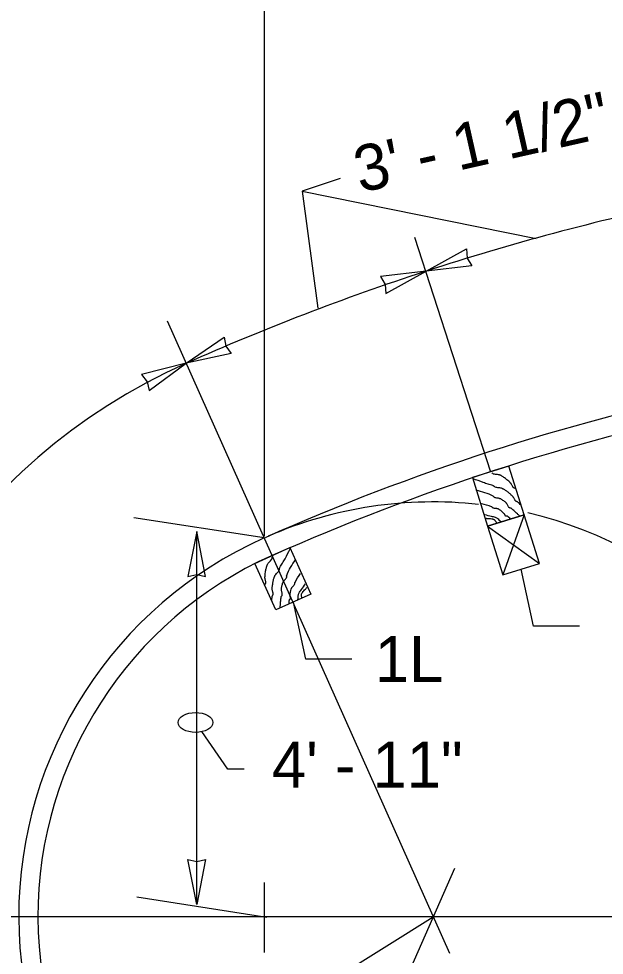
# Model space of a CAD drawing. Extents: x 1312564.2 to 1312581.5, y 1207298.4 to 1207352.6.
# Drawn here: x 1312566.218 to 1312567.233, y 1207306.924 to 1207308.547 of the extents above; entities that cross this region are included whole.
import ezdxf

# ---------------------------------------------------------------- set-up
doc = ezdxf.new("R2010")
doc.units = 0
for name, color, linetype in [('Level 13', 7, 'Continuous'), ('Level 14', 7, 'Continuous'), ('Level 15', 7, 'Continuous'), ('Level 20', 7, 'Continuous')]:
    doc.layers.add(name, color=color, linetype=linetype)

msp = doc.modelspace()

# ---------------------------------------------------------------- linework, layer by layer
at = {"layer": 'Level 13'}
for points in [[(1312567.0801831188, 1207307.7314976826), (1312567.0792387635, 1207307.732349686), (1312567.0788612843, 1207307.7326280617), (1312567.0784413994, 1207307.7328425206), (1312567.0775294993, 1207307.7331625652), (1312567.0766132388, 1207307.7334755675), (1312567.0761879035, 1207307.7336812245), (1312567.0758027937, 1207307.7339472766), (1312567.0750363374, 1207307.7347329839), (1312567.074407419, 1207307.7356371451), (1312567.0733904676, 1207307.7376581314), (1312567.0724084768, 1207307.7397248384), (1312567.07182326, 1207307.7406861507), (1312567.0711179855, 1207307.7415518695), (1312567.0701074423, 1207307.7425827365), (1312567.069083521, 1207307.74359835), (1312567.0626155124, 1207307.7493116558), (1312567.0579374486, 1207307.7526796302), (1312567.0554699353, 1207307.7542056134), (1312567.0542013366, 1207307.7549253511), (1312567.0529084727, 1207307.7556148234), (1312567.051294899, 1207307.7562446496), (1312567.0495871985, 1207307.7565974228), (1312567.0460449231, 1207307.7568778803), (1312567.042592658, 1207307.7572683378), (1312567.0409974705, 1207307.7577586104), (1312567.0395414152, 1207307.7585809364), (1312567.0380289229, 1207307.7597637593)], [(1312567.0888352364, 1207307.70378218), (1312567.083032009, 1207307.7090447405), (1312567.0822345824, 1207307.7095371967), (1312567.0813223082, 1207307.7098569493), (1312567.0804058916, 1207307.7101699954), (1312567.0795960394, 1207307.710642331), (1312567.078830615, 1207307.7114289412), (1312567.0782021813, 1207307.7123335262), (1312567.077185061, 1207307.7143543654), (1312567.0762022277, 1207307.716420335), (1312567.0752815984, 1207307.717828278), (1312567.0749112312, 1207307.7182469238), (1312567.0707931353, 1207307.7222832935), (1312567.0664286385, 1207307.726029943), (1312567.0617530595, 1207307.7294008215), (1312567.0592784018, 1207307.7309184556), (1312567.0580033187, 1207307.7316306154), (1312567.0567017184, 1207307.7323098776), (1312567.0550943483, 1207307.7329606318), (1312567.0534194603, 1207307.73338497), (1312567.0499658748, 1207307.7338472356), (1312567.0465384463, 1207307.7342823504), (1312567.0441038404, 1207307.7349431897), (1312567.0433346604, 1207307.7352759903), (1312567.0424580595, 1207307.7358484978), (1312567.0416447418, 1207307.7365543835), (1312567.040816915, 1207307.737235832), (1312567.0398967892, 1207307.7377350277), (1312567.0357424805, 1207307.7390843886), (1312567.031534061, 1207307.740295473), (1312567.0273303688, 1207307.7415275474), (1312567.0231902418, 1207307.7429398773), (1312567.0054866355, 1207307.7496751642)], [(1312567.0864377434, 1207307.684698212), (1312567.0822789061, 1207307.6887763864), (1312567.0797859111, 1207307.691163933), (1312567.077244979, 1207307.693502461), (1312567.0746719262, 1207307.6958037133), (1312567.072082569, 1207307.6980794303), (1312567.0717098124, 1207307.6983240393), (1312567.0712864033, 1207307.6984792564), (1312567.0703536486, 1207307.6986379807), (1312567.069416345, 1207307.6987885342), (1312567.068606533, 1207307.6991638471), (1312567.0681587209, 1207307.6995654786), (1312567.067754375, 1207307.700007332), (1312567.0670521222, 1207307.700990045), (1312567.0659056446, 1207307.7031998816), (1312567.0647837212, 1207307.7054468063), (1312567.0637277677, 1207307.7069478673), (1312567.0633029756, 1207307.7073842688), (1312567.0610276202, 1207307.7093902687), (1312567.0586327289, 1207307.711257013), (1312567.0561122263, 1207307.7129612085), (1312567.053460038, 1207307.7144795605), (1312567.0521457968, 1207307.7150303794), (1312567.05076426, 1207307.7153972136), (1312567.0478969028, 1207307.7158235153), (1312567.0450531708, 1207307.7162476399), (1312567.0437011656, 1207307.7166117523), (1312567.042428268, 1207307.7171587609), (1312567.041880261, 1207307.7176321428), (1312567.0414293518, 1207307.7182549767), (1312567.0409638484, 1207307.7188537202), (1312567.0403720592, 1207307.7192548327), (1312567.0111425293, 1207307.729577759)], [(1312567.070334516, 1207307.6796711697), (1312567.0646377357, 1207307.6847546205), (1312567.0643591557, 1207307.6849131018), (1312567.0640345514, 1207307.6849647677), (1312567.0633073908, 1207307.6848879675), (1312567.0625765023, 1207307.684804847), (1312567.0619621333, 1207307.6849960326), (1312567.061754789, 1207307.6851866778), (1312567.0615703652, 1207307.6853973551), (1312567.0612578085, 1207307.685868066), (1312567.0607705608, 1207307.6869317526), (1312567.0603008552, 1207307.6880152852), (1312567.0600102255, 1207307.6885108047), (1312567.0596491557, 1207307.6889468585), (1312567.058449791, 1207307.6901151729), (1312567.0572263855, 1207307.6912654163), (1312567.05467958, 1207307.6934675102), (1312567.050504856, 1207307.6963589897), (1312567.04975653, 1207307.696775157), (1312567.04899087, 1207307.6971688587), (1312567.0479593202, 1207307.6975677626), (1312567.0468838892, 1207307.6978082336), (1312567.044666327, 1207307.6980191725), (1312567.0424680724, 1207307.6982122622), (1312567.0409101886, 1207307.6985923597), (1312567.040662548, 1207307.6986893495), (1312567.0404190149, 1207307.6987980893), (1312567.0397158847, 1207307.6992674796), (1312567.039069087, 1207307.699857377), (1312567.0384068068, 1207307.7004186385), (1312567.0376572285, 1207307.700802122), (1312567.020162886, 1207307.7060446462)], [(1312567.054269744, 1207307.674656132), (1312567.0522416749, 1207307.6764684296), (1312567.0517878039, 1207307.6768861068), (1312567.051338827, 1207307.677319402), (1312567.048639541, 1207307.67999126), (1312567.0466931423, 1207307.681506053), (1312567.04448496, 1207307.682466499), (1312567.037516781, 1207307.6841813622), (1312567.0259177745, 1207307.6870358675)], [(1312567.046658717, 1207307.6722801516), (1312567.045875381, 1207307.673895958), (1312567.045060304, 1207307.675464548), (1312567.044122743, 1207307.6768509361), (1312567.0435796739, 1207307.6774336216), (1312567.0432846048, 1207307.6776899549), (1312567.0431305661, 1207307.6778084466), (1312567.0430518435, 1207307.6778651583), (1312567.0430120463, 1207307.6778928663), (1312567.0429920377, 1207307.6779065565), (1312567.0429719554, 1207307.6779201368), (1312567.0426034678, 1207307.6781535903), (1312567.0422221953, 1207307.6783680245), (1312567.0414238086, 1207307.6787435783), (1312567.0397012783, 1207307.6793076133), (1312567.0358940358, 1207307.679896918), (1312567.0318721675, 1207307.6801669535), (1312567.0298813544, 1207307.6803319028), (1312567.027957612, 1207307.6805966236)], [(1312566.6566299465, 1207307.5381493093), (1312566.657468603, 1207307.5459383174), (1312566.6577371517, 1207307.5468362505), (1312566.6582062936, 1207307.547681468), (1312566.6586829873, 1207307.5485244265), (1312566.6589741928, 1207307.5494155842), (1312566.6590233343, 1207307.5505120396), (1312566.6588917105, 1207307.551605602), (1312566.6583086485, 1207307.5537915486), (1312566.6576699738, 1207307.5559884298), (1312566.6574221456, 1207307.5576522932), (1312566.657420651, 1207307.5582112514), (1312566.6578151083, 1207307.5639641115), (1312566.6585862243, 1207307.5696642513), (1312566.6598395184, 1207307.5752903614), (1312566.6606799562, 1207307.5780689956), (1312566.661159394, 1207307.5794485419), (1312566.6616805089, 1207307.5808211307), (1312566.662449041, 1207307.5823756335), (1312566.6634184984, 1207307.5838058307), (1312566.6656917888, 1207307.586446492), (1312566.6679635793, 1207307.589049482), (1312566.669343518, 1207307.5911613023), (1312566.6696970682, 1207307.5919211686), (1312566.6699715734, 1207307.592931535), (1312566.6701101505, 1207307.5939995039), (1312566.6702758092, 1207307.5950588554), (1312566.67063156, 1207307.59604337), (1312566.6728388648, 1207307.5998125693), (1312566.6751785, 1207307.6035144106), (1312566.6775006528, 1207307.6072287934), (1312566.679655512, 1207307.6110356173), (1312566.6884073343, 1207307.627834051)], [(1312566.6446750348, 1207307.5646084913), (1312566.6448144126, 1207307.5658727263), (1312566.6449114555, 1207307.566331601), (1312566.6450826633, 1207307.5667709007), (1312566.6455513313, 1207307.5676160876), (1312566.6460279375, 1207307.5684589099), (1312566.6462090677, 1207307.568895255), (1312566.6463200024, 1207307.5693499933), (1312566.6463705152, 1207307.57044646), (1312566.646239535, 1207307.5715400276), (1312566.6456562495, 1207307.573725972), (1312566.645016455, 1207307.5759228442), (1312566.644814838, 1207307.5770300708), (1312566.6447664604, 1207307.5781456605), (1312566.6448364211, 1207307.579587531), (1312566.6449265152, 1207307.5810268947), (1312566.6459623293, 1207307.5895945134), (1312566.6472194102, 1207307.5952201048), (1312566.648048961, 1207307.5980002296), (1312566.648518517, 1207307.5993811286), (1312566.6490263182, 1207307.6007555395), (1312566.6498133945, 1207307.6022985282), (1312566.6508549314, 1207307.6036970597), (1312566.653315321, 1207307.6062608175), (1312566.6556353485, 1207307.6088469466), (1312566.6565014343, 1207307.6102734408), (1312566.6570428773, 1207307.611855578), (1312566.6573869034, 1207307.6137445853)], [(1312566.6711045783, 1207307.52548318), (1312566.6715016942, 1207307.5312943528), (1312566.6717776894, 1207307.5347351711), (1312566.67212208, 1207307.5381712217), (1312566.6725152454, 1207307.5416007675), (1312566.6729375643, 1207307.5450220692), (1312566.6730535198, 1207307.5454525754), (1312566.6732667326, 1207307.545849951), (1312566.6738581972, 1207307.5465884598), (1312566.6744584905, 1207307.5473238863), (1312566.6748141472, 1207307.5481425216), (1312566.6748818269, 1207307.5487402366), (1312566.6748902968, 1207307.549339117), (1312566.6747619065, 1207307.5505401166), (1312566.6741498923, 1207307.552953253), (1312566.6734948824, 1207307.5553777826), (1312566.673286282, 1207307.5572011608), (1312566.6733136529, 1207307.5578095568), (1312566.673680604, 1207307.56082064), (1312566.674229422, 1207307.5638071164), (1312566.6749801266, 1207307.5667556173), (1312566.6759527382, 1207307.5696527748), (1312566.6765686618, 1207307.570937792), (1312566.6773571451, 1207307.572130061), (1312566.6792163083, 1207307.574354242), (1312566.6810592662, 1207307.5765610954), (1312566.6818274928, 1207307.5777317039), (1312566.6824150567, 1207307.5789863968), (1312566.6825099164, 1207307.5797043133), (1312566.6824328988, 1207307.5804693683), (1312566.682382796, 1207307.5812261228), (1312566.6825584, 1207307.5819191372), (1312566.697538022, 1207307.6090583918)], [(1312566.6864778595, 1207307.5324292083), (1312566.6873560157, 1207307.5400136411), (1312566.6874588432, 1207307.5403172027), (1312566.6876670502, 1207307.5405715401), (1312566.688261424, 1207307.5409974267), (1312566.6888627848, 1207307.5414210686), (1312566.689194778, 1207307.5419722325), (1312566.6892230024, 1207307.5422524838), (1312566.689220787, 1207307.5425324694), (1312566.6891414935, 1207307.5430919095), (1312566.6887986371, 1207307.5442105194), (1312566.6884294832, 1207307.5453323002), (1312566.688317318, 1207307.545895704), (1312566.688297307, 1207307.5464614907), (1312566.6884170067, 1207307.5481315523), (1312566.6885666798, 1207307.5498040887), (1312566.6890061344, 1207307.5531420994), (1312566.6902037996, 1207307.5580771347), (1312566.6904863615, 1207307.5588854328), (1312566.6907968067, 1207307.5596884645), (1312566.6913024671, 1207307.5606720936), (1312566.6919462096, 1207307.5615665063), (1312566.6934629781, 1207307.5631979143), (1312566.694977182, 1207307.5648031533), (1312566.695888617, 1207307.5661225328), (1312566.6960091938, 1207307.5663595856), (1312566.696118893, 1207307.5666026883), (1312566.6963323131, 1207307.567420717), (1312566.6964235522, 1207307.5682913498), (1312566.6965453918, 1207307.569150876), (1312566.696850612, 1207307.5699355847), (1312566.7064381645, 1207307.585479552)], [(1312566.7018144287, 1207307.5393586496), (1312566.7021253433, 1207307.542060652), (1312566.702186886, 1207307.5426743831), (1312566.7022343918, 1207307.543296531), (1312566.7024755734, 1207307.5470868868), (1312566.7029231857, 1207307.5495123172), (1312566.7039348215, 1207307.5516975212), (1312566.7080017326, 1207307.5576099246), (1312566.714771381, 1207307.5674515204)], [(1312566.7090804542, 1207307.5426416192), (1312566.708591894, 1207307.544369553), (1312566.7081584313, 1207307.5460833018), (1312566.70793758, 1207307.5477423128), (1312566.7079561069, 1207307.5485386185), (1312566.7080062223, 1207307.5489262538), (1312566.7080425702, 1207307.549117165), (1312566.7080637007, 1207307.549211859), (1312566.708075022, 1207307.5492590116), (1312566.708080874, 1207307.5492825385), (1312566.7080868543, 1207307.5493060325), (1312566.708207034, 1207307.5497253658), (1312566.7083494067, 1207307.550138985), (1312566.7086963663, 1207307.5509502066), (1312566.7096085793, 1207307.5525164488), (1312566.7120616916, 1207307.5554870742), (1312566.7148873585, 1207307.5583617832), (1312566.716265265, 1207307.5598081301), (1312566.7175267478, 1207307.5612844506)]]:
    msp.add_spline(points, degree=3, dxfattribs=at)
at = {"layer": 'Level 14'}
for p, q in [((1312567.0940508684, 1207307.6870748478), (1312567.0571052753, 1207307.5828537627)), ((1312567.0307398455, 1207307.6673106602), (1312567.120416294, 1207307.6026179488))]:
    msp.add_line(p, q, dxfattribs=at)
at = {"layer": 'Level 15'}
for p, q in [((1312566.6440553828, 1207307.6503023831), (1312566.6440553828, 1207308.7609998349)), ((1312566.709108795, 1207308.2480134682), (1312567.114736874, 1207308.165731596)), ((1312566.9039208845, 1207308.1684178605), (1312567.0360299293, 1207307.7616496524)), ((1312566.9650794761, 1207306.9268875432), (1312566.4758216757, 1207308.0225754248)), ((1312566.6434698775, 1207307.6471289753), (1312566.4176774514, 1207307.6820834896)), ((1312566.5265781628, 1207307.011658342), (1312566.5265781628, 1207307.6582362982)), ((1312567.1104634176, 1207307.4938315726), (1312567.0887607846, 1207307.5927358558)), ((1312566.715759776, 1207307.4369494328), (1312566.694057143, 1207307.535853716)), ((1312567.1901920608, 1207307.4938315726), (1312567.1104634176, 1207307.4938315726)), ((1312566.7954884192, 1207307.4369494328), (1312566.715759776, 1207307.4369494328)), ((1312566.9733172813, 1207307.0740279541), (1312566.479341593, 1207305.9575790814)), ((1312566.6440553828, 1207306.9284557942), (1312566.6440553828, 1207307.049939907)), ((1312566.648261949, 1207306.9894545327), (1312566.4224695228, 1207307.024409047)), ((1312565.7519709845, 1207306.9908537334), (1312575.0870337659, 1207306.9908537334)), ((1312566.9365166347, 1207306.9908537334), (1312566.9365166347, 1207306.9908537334)), ((1312566.9365166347, 1207306.989771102), (1312566.3224773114, 1207306.606878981))]:
    msp.add_line(p, q, dxfattribs=at)
for points in [[(1312566.7748863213, 1207308.2699553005), (1312566.709108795, 1207308.2480134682), (1312566.736516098, 1207308.045051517)], [(1312566.608810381, 1207307.2462443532), (1312566.5806613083, 1207307.2462443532), (1312566.5353833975, 1207307.3113788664)]]:
    msp.add_lwpolyline(points, dxfattribs=at)
for points in [[(1312566.924196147, 1207308.109245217), (1312566.9941623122, 1207308.1477280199), (1312566.995382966, 1207308.1319852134), (1312567.0035148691, 1207308.118450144)], [(1312566.924196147, 1207308.109245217), (1312566.84490005, 1207308.0998473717), (1312566.8530648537, 1207308.0863321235), (1312566.8543237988, 1207308.0705923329)], [(1312566.50826333, 1207307.9495808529), (1312566.5739385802, 1207307.995000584), (1312566.5767588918, 1207307.9794644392), (1312566.586229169, 1207307.9668295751)], [(1312566.50826333, 1207307.9495808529), (1312566.4308206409, 1207307.9301175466), (1312566.4406470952, 1207307.9177576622), (1312566.4439089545, 1207307.9023081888)], [(1312567.0676854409, 1207307.7715317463), (1312567.0043744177, 1207307.7517675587), (1312567.0307398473, 1207307.667310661), (1312567.0940508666, 1207307.6870748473)], [(1312567.0940508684, 1207307.6870748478), (1312567.0307398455, 1207307.6673106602), (1312567.0571052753, 1207307.5828537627), (1312567.120416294, 1207307.6026179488)], [(1312566.5265781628, 1207307.6582362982), (1312566.511210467, 1207307.5798779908), (1312566.5265781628, 1207307.5835056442), (1312566.541945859, 1207307.5798779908)], [(1312566.6274065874, 1207307.602827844), (1312566.6878477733, 1207307.6301366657), (1312566.7242777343, 1207307.549508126), (1312566.6638365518, 1207307.522199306)], [(1312566.5265781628, 1207307.011658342), (1312566.511210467, 1207307.0900166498), (1312566.5265781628, 1207307.0863889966), (1312566.541945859, 1207307.0900166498)]]:
    msp.add_lwpolyline(points, close=True, dxfattribs=at)
for centre, radius, start, end in [((1312568.259140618, 1207304.0100611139), 4.311077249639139, 101.91135088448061, 108.03841031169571), ((1312568.259140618, 1207304.0100611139), 4.311077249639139, 108.06980602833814, 113.96224153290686), ((1312568.259140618, 1207304.0100611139), 3.9794559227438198, 90.01657105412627, 113.93173117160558), ((1312566.9365166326, 1207306.9908537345), 1.0501784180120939, 114.09858116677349, 245.8728399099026), ((1312568.2582266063, 1207304.0093876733), 3.946293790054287, 90.01657105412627, 113.93173117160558), ((1312566.9365166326, 1207306.9908537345), 0.7185570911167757, 83.71210278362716, 113.46628666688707), ((1312566.9365166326, 1207306.9908537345), 0.7185570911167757, 246.6315280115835, 76.79679181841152), ((1312566.9365166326, 1207306.9908537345), 0.7185570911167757, 114.173524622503, 246.08075396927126), ((1312566.9365166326, 1207306.9908537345), 0.6853949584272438, 114.173524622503, 246.08075396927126)]:
    msp.add_arc(centre, radius, start, end, dxfattribs=at)
msp.add_ellipse((1312566.5243631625, 1207307.3272320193), major_axis=(-0.02989824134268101, 3.6614785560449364e-18), ratio=0.5773502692, dxfattribs=at)

# ---------------------------------------------------------------- texts
at = {"layer": 'Level 20'}
msp.add_text('3\' - 1 1/2"', height=0.07972865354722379, rotation=12.688191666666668, dxfattribs=at).set_placement((1312566.8097123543, 1207308.2449337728))
for s, p in [('1L', (1312566.8353527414, 1207307.397085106)), ('4\' - 11"', (1312566.6568219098, 1207307.2144186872))]:
    msp.add_text(s, height=0.07972865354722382, dxfattribs=at).set_placement(p)

doc.saveas('drawing.dxf')
